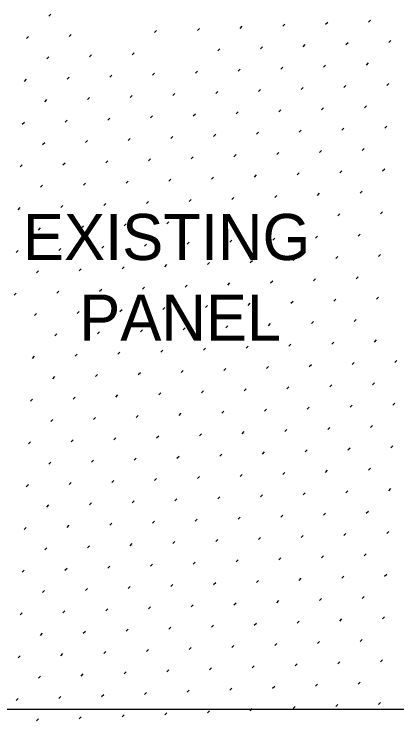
# Model space of a CAD drawing. Extents: x 49991.4 to 50021, y 49987.6 to 50011.4.
# Drawn here: x 50008.575 to 50009.239, y 49994.77 to 49995.997 of the extents above; entities that cross this region are included whole.
import ezdxf

# ---------------------------------------------------------------- set-up
doc = ezdxf.new("R2010")
doc.units = 0
for name, color, linetype in [('Level 1', 7, 'Continuous'), ('Level 10', 7, 'Continuous'), ('Level 2', 7, 'Continuous')]:
    doc.layers.add(name, color=color, linetype=linetype)

msp = doc.modelspace()

# ---------------------------------------------------------------- linework, layer by layer
at = {"layer": 'Level 1'}
msp.add_line((50007.9348, 49994.7903), (50009.8098, 49994.7903), dxfattribs=at)
at = {"layer": 'Level 10'}
for p, q in [((50008.6348, 49995.9936), (50008.6383, 49995.9972)), ((50009.1157, 49995.9795), (50009.1192, 49995.9831)), ((50009.1899, 49995.9831), (50009.1935, 49995.9866)), ((50008.8187, 49995.9654), (50008.8222, 49995.9689)), ((50008.8929, 49995.9689), (50008.8965, 49995.9724)), ((50008.9672, 49995.9724), (50008.9707, 49995.976)), ((50009.0414, 49995.976), (50009.045, 49995.9795)), ((50008.5959, 49995.9547), (50008.5994, 49995.9583)), ((50008.6702, 49995.9583), (50008.6737, 49995.9618)), ((50009.0768, 49995.9406), (50009.0803, 49995.9442)), ((50009.151, 49995.9442), (50009.1546, 49995.9477)), ((50009.2253, 49995.9477), (50009.2288, 49995.9513)), ((50008.9283, 49995.9335), (50008.9318, 49995.9371)), ((50009.0025, 49995.9371), (50009.0061, 49995.9406)), ((50008.6313, 49995.9194), (50008.6348, 49995.9229)), ((50008.7055, 49995.9229), (50008.7091, 49995.9265)), ((50008.7798, 49995.9265), (50008.7833, 49995.93)), ((50009.1121, 49995.9053), (50009.1157, 49995.9088)), ((50009.1864, 49995.9088), (50009.1899, 49995.9124)), ((50008.8894, 49995.8947), (50008.8929, 49995.8982)), ((50008.9636, 49995.8982), (50008.9672, 49995.9017)), ((50009.0379, 49995.9017), (50009.0414, 49995.9053)), ((50008.5924, 49995.8805), (50008.5959, 49995.884)), ((50008.6666, 49995.884), (50008.6702, 49995.8876)), ((50008.7409, 49995.8876), (50008.7444, 49995.8911)), ((50008.8151, 49995.8911), (50008.8187, 49995.8946)), ((50009.1475, 49995.8699), (50009.151, 49995.8735)), ((50009.2218, 49995.8735), (50009.2253, 49995.877)), ((50008.8505, 49995.8558), (50008.854, 49995.8593)), ((50008.9247, 49995.8593), (50008.9283, 49995.8628)), ((50008.999, 49995.8628), (50009.0025, 49995.8664)), ((50009.0732, 49995.8664), (50009.0768, 49995.8699)), ((50008.6277, 49995.8451), (50008.6313, 49995.8487)), ((50008.702, 49995.8487), (50008.7055, 49995.8522)), ((50008.7762, 49995.8522), (50008.7798, 49995.8557)), ((50009.1086, 49995.831), (50009.1121, 49995.8346)), ((50009.1829, 49995.8346), (50009.1864, 49995.8381)), ((50008.8858, 49995.8204), (50008.8894, 49995.8239)), ((50008.9601, 49995.8239), (50008.9636, 49995.8275)), ((50009.0343, 49995.8275), (50009.0379, 49995.831)), ((50008.5888, 49995.8062), (50008.5924, 49995.8098)), ((50008.6631, 49995.8098), (50008.6666, 49995.8133)), ((50008.7373, 49995.8133), (50008.7409, 49995.8168)), ((50008.8116, 49995.8169), (50008.8151, 49995.8204)), ((50009.144, 49995.7957), (50009.1475, 49995.7992)), ((50009.2182, 49995.7992), (50009.2217, 49995.8027)), ((50008.8469, 49995.7815), (50008.8505, 49995.785)), ((50008.9212, 49995.785), (50008.9247, 49995.7886)), ((50008.9954, 49995.7886), (50008.999, 49995.7921)), ((50009.0697, 49995.7921), (50009.0732, 49995.7957)), ((50008.6242, 49995.7709), (50008.6277, 49995.7744)), ((50008.6984, 49995.7744), (50008.702, 49995.778)), ((50008.7727, 49995.778), (50008.7762, 49995.7815)), ((50009.1051, 49995.7568), (50009.1086, 49995.7603)), ((50009.1793, 49995.7603), (50009.1828, 49995.7639)), ((50008.8823, 49995.7461), (50008.8858, 49995.7497)), ((50008.9565, 49995.7497), (50008.9601, 49995.7532)), ((50009.0308, 49995.7532), (50009.0343, 49995.7568)), ((50008.5853, 49995.732), (50008.5888, 49995.7355)), ((50008.6595, 49995.7355), (50008.6631, 49995.7391)), ((50008.7338, 49995.7391), (50008.7373, 49995.7426)), ((50008.808, 49995.7426), (50008.8116, 49995.7461)), ((50009.1404, 49995.7214), (50009.1439, 49995.725)), ((50009.2147, 49995.725), (50009.2182, 49995.7285)), ((50008.8434, 49995.7072), (50008.8469, 49995.7108)), ((50008.9177, 49995.7108), (50008.9212, 49995.7143)), ((50008.9919, 49995.7143), (50008.9954, 49995.7179)), ((50009.0662, 49995.7179), (50009.0697, 49995.7214)), ((50008.6206, 49995.6966), (50008.6242, 49995.7002)), ((50008.6949, 49995.7002), (50008.6984, 49995.7037)), ((50008.7691, 49995.7037), (50008.7727, 49995.7072)), ((50009.1758, 49995.6861), (50009.1793, 49995.6896)), ((50008.8788, 49995.6719), (50008.8823, 49995.6754)), ((50008.953, 49995.6754), (50008.9565, 49995.679)), ((50009.0273, 49995.679), (50009.0308, 49995.6825)), ((50009.1015, 49995.6825), (50009.105, 49995.6861)), ((50008.656, 49995.6613), (50008.6595, 49995.6648)), ((50008.7302, 49995.6648), (50008.7338, 49995.6683)), ((50008.8045, 49995.6683), (50008.808, 49995.6719)), ((50008.5817, 49995.6577), (50008.5853, 49995.6613)), ((50009.1369, 49995.6472), (50009.1404, 49995.6507)), ((50009.2111, 49995.6507), (50009.2147, 49995.6542)), ((50008.9141, 49995.6365), (50008.9176, 49995.6401)), ((50008.9884, 49995.6401), (50008.9919, 49995.6436)), ((50009.0626, 49995.6436), (50009.0662, 49995.6472)), ((50008.6171, 49995.6224), (50008.6206, 49995.6259)), ((50008.6913, 49995.6259), (50008.6949, 49995.6294)), ((50008.7656, 49995.6295), (50008.7691, 49995.633)), ((50008.8399, 49995.633), (50008.8434, 49995.6365)), ((50009.1722, 49995.6118), (50009.1758, 49995.6153)), ((50008.8752, 49995.5976), (50008.8787, 49995.6012)), ((50008.9495, 49995.6012), (50008.953, 49995.6047)), ((50009.0237, 49995.6047), (50009.0273, 49995.6083)), ((50009.098, 49995.6083), (50009.1015, 49995.6118)), ((50008.6525, 49995.587), (50008.656, 49995.5905)), ((50008.7267, 49995.5906), (50008.7302, 49995.5941)), ((50008.801, 49995.5941), (50008.8045, 49995.5976)), ((50008.5782, 49995.5835), (50008.5817, 49995.587)), ((50009.1333, 49995.5729), (50009.1369, 49995.5764)), ((50009.2076, 49995.5765), (50009.2111, 49995.58)), ((50008.9106, 49995.5623), (50008.9141, 49995.5658)), ((50008.9848, 49995.5658), (50008.9884, 49995.5694)), ((50009.0591, 49995.5694), (50009.0626, 49995.5729)), ((50008.6136, 49995.5481), (50008.6171, 49995.5516)), ((50008.6878, 49995.5517), (50008.6913, 49995.5552)), ((50008.7621, 49995.5552), (50008.7656, 49995.5587)), ((50008.8363, 49995.5587), (50008.8398, 49995.5623)), ((50009.1687, 49995.5376), (50009.1722, 49995.5411)), ((50008.8717, 49995.5234), (50008.8752, 49995.5269)), ((50008.9459, 49995.5269), (50008.9495, 49995.5305)), ((50009.0202, 49995.5305), (50009.0237, 49995.534)), ((50009.0944, 49995.534), (50009.098, 49995.5375)), ((50008.6489, 49995.5128), (50008.6524, 49995.5163)), ((50008.7232, 49995.5163), (50008.7267, 49995.5198)), ((50008.7974, 49995.5198), (50008.801, 49995.5234)), ((50008.5747, 49995.5092), (50008.5782, 49995.5128)), ((50009.1298, 49995.4987), (50009.1333, 49995.5022)), ((50009.204, 49995.5022), (50009.2076, 49995.5057)), ((50008.907, 49995.488), (50008.9106, 49995.4916)), ((50008.9813, 49995.4916), (50008.9848, 49995.4951)), ((50009.0555, 49995.4951), (50009.0591, 49995.4987)), ((50008.6843, 49995.4774), (50008.6878, 49995.4809)), ((50008.7585, 49995.4809), (50008.7621, 49995.4845)), ((50008.8328, 49995.4845), (50008.8363, 49995.488)), ((50008.61, 49995.4739), (50008.6135, 49995.4774)), ((50009.1651, 49995.4633), (50009.1687, 49995.4668)), ((50008.9424, 49995.4527), (50008.9459, 49995.4562)), ((50009.0166, 49995.4562), (50009.0202, 49995.4598)), ((50009.0909, 49995.4598), (50009.0944, 49995.4633)), ((50008.6454, 49995.4385), (50008.6489, 49995.442)), ((50008.7196, 49995.442), (50008.7232, 49995.4456)), ((50008.7939, 49995.4456), (50008.7974, 49995.4491)), ((50008.8681, 49995.4491), (50008.8717, 49995.4527)), ((50009.2005, 49995.4279), (50009.204, 49995.4315)), ((50008.9035, 49995.4138), (50008.907, 49995.4173)), ((50008.9777, 49995.4173), (50008.9813, 49995.4209)), ((50009.052, 49995.4209), (50009.0555, 49995.4244)), ((50009.1262, 49995.4244), (50009.1298, 49995.4279)), ((50008.6807, 49995.4031), (50008.6843, 49995.4067)), ((50008.755, 49995.4067), (50008.7585, 49995.4102)), ((50008.8292, 49995.4102), (50008.8328, 49995.4138)), ((50008.6065, 49995.3996), (50008.61, 49995.4031)), ((50009.1616, 49995.389), (50009.1651, 49995.3926)), ((50009.2359, 49995.3926), (50009.2394, 49995.3961)), ((50008.9388, 49995.3784), (50008.9424, 49995.382)), ((50009.0131, 49995.382), (50009.0166, 49995.3855)), ((50009.0873, 49995.3855), (50009.0909, 49995.389)), ((50008.6418, 49995.3643), (50008.6454, 49995.3678)), ((50008.7161, 49995.3678), (50008.7196, 49995.3713)), ((50008.7903, 49995.3713), (50008.7939, 49995.3749)), ((50008.8646, 49995.3749), (50008.8681, 49995.3784)), ((50009.197, 49995.3537), (50009.2005, 49995.3572)), ((50008.8999, 49995.3395), (50008.9035, 49995.3431)), ((50008.9742, 49995.3431), (50008.9777, 49995.3466)), ((50009.0484, 49995.3466), (50009.052, 49995.3501)), ((50009.1227, 49995.3502), (50009.1262, 49995.3537)), ((50008.6772, 49995.3289), (50008.6807, 49995.3324)), ((50008.7514, 49995.3324), (50008.755, 49995.336)), ((50008.8257, 49995.336), (50008.8292, 49995.3395)), ((50008.6029, 49995.3254), (50008.6065, 49995.3289)), ((50009.1581, 49995.3148), (50009.1616, 49995.3183)), ((50009.2323, 49995.3183), (50009.2358, 49995.3219)), ((50008.9353, 49995.3042), (50008.9388, 49995.3077)), ((50009.0095, 49995.3077), (50009.0131, 49995.3112)), ((50009.0838, 49995.3113), (50009.0873, 49995.3148)), ((50008.6383, 49995.29), (50008.6418, 49995.2935)), ((50008.7125, 49995.2935), (50008.7161, 49995.2971)), ((50008.7868, 49995.2971), (50008.7903, 49995.3006)), ((50008.861, 49995.3006), (50008.8646, 49995.3042)), ((50009.1934, 49995.2794), (50009.1969, 49995.283)), ((50008.9706, 49995.2688), (50008.9742, 49995.2723)), ((50009.0449, 49995.2724), (50009.0484, 49995.2759)), ((50009.1192, 49995.2759), (50009.1227, 49995.2794)), ((50008.6736, 49995.2546), (50008.6772, 49995.2582)), ((50008.7479, 49995.2582), (50008.7514, 49995.2617)), ((50008.8221, 49995.2617), (50008.8257, 49995.2653)), ((50008.8964, 49995.2653), (50008.8999, 49995.2688)), ((50008.5994, 49995.2511), (50008.6029, 49995.2546)), ((50009.2288, 49995.2441), (50009.2323, 49995.2476)), ((50008.9318, 49995.2299), (50008.9353, 49995.2335)), ((50009.006, 49995.2335), (50009.0095, 49995.237)), ((50009.0803, 49995.237), (50009.0838, 49995.2405)), ((50009.1545, 49995.2405), (50009.158, 49995.2441)), ((50008.709, 49995.2193), (50008.7125, 49995.2228)), ((50008.7832, 49995.2228), (50008.7868, 49995.2264)), ((50008.8575, 49995.2264), (50008.861, 49995.2299)), ((50008.6347, 49995.2157), (50008.6383, 49995.2193)), ((50009.1899, 49995.2052), (50009.1934, 49995.2087)), ((50008.9671, 49995.1946), (50008.9706, 49995.1981)), ((50009.0414, 49995.1981), (50009.0449, 49995.2016)), ((50009.1156, 49995.2016), (50009.1191, 49995.2052)), ((50008.6701, 49995.1804), (50008.6736, 49995.1839)), ((50008.7443, 49995.1839), (50008.7479, 49995.1875)), ((50008.8186, 49995.1875), (50008.8221, 49995.191)), ((50008.8929, 49995.191), (50008.8964, 49995.1946)), ((50008.5958, 49995.1768), (50008.5994, 49995.1804)), ((50009.2252, 49995.1698), (50009.2288, 49995.1734)), ((50008.9282, 49995.1557), (50008.9317, 49995.1592)), ((50009.0025, 49995.1592), (50009.006, 49995.1627)), ((50009.0767, 49995.1627), (50009.0803, 49995.1663)), ((50009.151, 49995.1663), (50009.1545, 49995.1698)), ((50008.7054, 49995.145), (50008.709, 49995.1486)), ((50008.7797, 49995.1486), (50008.7832, 49995.1521)), ((50008.854, 49995.1521), (50008.8575, 49995.1557)), ((50008.6312, 49995.1415), (50008.6347, 49995.145)), ((50009.1863, 49995.1309), (50009.1899, 49995.1345)), ((50008.9636, 49995.1203), (50008.9671, 49995.1238)), ((50009.0378, 49995.1238), (50009.0414, 49995.1274)), ((50009.1121, 49995.1274), (50009.1156, 49995.1309)), ((50008.6666, 49995.1061), (50008.6701, 49995.1097)), ((50008.7408, 49995.1097), (50008.7443, 49995.1132)), ((50008.8151, 49995.1132), (50008.8186, 49995.1168)), ((50008.8893, 49995.1168), (50008.8928, 49995.1203)), ((50008.5923, 49995.1026), (50008.5958, 49995.1061)), ((50009.2217, 49995.0956), (50009.2252, 49995.0991)), ((50008.9247, 49995.0814), (50008.9282, 49995.0849)), ((50008.9989, 49995.085), (50009.0025, 49995.0885)), ((50009.0732, 49995.0885), (50009.0767, 49995.092)), ((50009.1474, 49995.092), (50009.151, 49995.0956)), ((50008.7019, 49995.0708), (50008.7054, 49995.0743)), ((50008.7762, 49995.0743), (50008.7797, 49995.0779)), ((50008.8504, 49995.0779), (50008.8539, 49995.0814)), ((50008.6277, 49995.0672), (50008.6312, 49995.0708)), ((50008.96, 49995.0461), (50008.9636, 49995.0496)), ((50009.0343, 49995.0496), (50009.0378, 49995.0531)), ((50009.1085, 49995.0531), (50009.1121, 49995.0567)), ((50009.1828, 49995.0567), (50009.1863, 49995.0602)), ((50008.7373, 49995.0354), (50008.7408, 49995.039)), ((50008.8115, 49995.039), (50008.8151, 49995.0425)), ((50008.8858, 49995.0425), (50008.8893, 49995.046)), ((50008.5888, 49995.0283), (50008.5923, 49995.0319)), ((50008.663, 49995.0319), (50008.6665, 49995.0354)), ((50009.2181, 49995.0213), (50009.2217, 49995.0249)), ((50008.9954, 49995.0107), (50008.9989, 49995.0142)), ((50009.0696, 49995.0142), (50009.0732, 49995.0178)), ((50009.1439, 49995.0178), (50009.1474, 49995.0213)), ((50008.6984, 49994.9965), (50008.7019, 49995.0001)), ((50008.7726, 49995.0001), (50008.7762, 49995.0036)), ((50008.8469, 49995.0036), (50008.8504, 49995.0071)), ((50008.9211, 49995.0072), (50008.9247, 49995.0107)), ((50008.6241, 49994.993), (50008.6276, 49994.9965)), ((50008.9565, 49994.9718), (50008.96, 49994.9753)), ((50009.0307, 49994.9753), (50009.0343, 49994.9789)), ((50009.105, 49994.9789), (50009.1085, 49994.9824)), ((50009.1792, 49994.9824), (50009.1828, 49994.986)), ((50008.7337, 49994.9612), (50008.7373, 49994.9647)), ((50008.808, 49994.9647), (50008.8115, 49994.9683)), ((50008.8822, 49994.9683), (50008.8858, 49994.9718)), ((50008.5852, 49994.9541), (50008.5887, 49994.9576)), ((50008.6595, 49994.9576), (50008.663, 49994.9612)), ((50009.2146, 49994.9471), (50009.2181, 49994.9506)), ((50008.9918, 49994.9364), (50008.9954, 49994.94)), ((50009.0661, 49994.94), (50009.0696, 49994.9435)), ((50009.1403, 49994.9435), (50009.1439, 49994.9471)), ((50008.6948, 49994.9223), (50008.6984, 49994.9258)), ((50008.7691, 49994.9258), (50008.7726, 49994.9294)), ((50008.8433, 49994.9294), (50008.8469, 49994.9329)), ((50008.9176, 49994.9329), (50008.9211, 49994.9364)), ((50008.6206, 49994.9187), (50008.6241, 49994.9223)), ((50008.9529, 49994.8975), (50008.9565, 49994.9011)), ((50009.0272, 49994.9011), (50009.0307, 49994.9046)), ((50009.1014, 49994.9046), (50009.105, 49994.9082)), ((50009.1757, 49994.9082), (50009.1792, 49994.9117)), ((50008.7302, 49994.8869), (50008.7337, 49994.8905)), ((50008.8044, 49994.8905), (50008.808, 49994.894)), ((50008.8787, 49994.894), (50008.8822, 49994.8975)), ((50008.5817, 49994.8798), (50008.5852, 49994.8834)), ((50008.6559, 49994.8834), (50008.6595, 49994.8869)), ((50009.2111, 49994.8728), (50009.2146, 49994.8764)), ((50008.9883, 49994.8622), (50008.9918, 49994.8657)), ((50009.0625, 49994.8657), (50009.0661, 49994.8693)), ((50009.1368, 49994.8693), (50009.1403, 49994.8728)), ((50008.7655, 49994.8516), (50008.7691, 49994.8551)), ((50008.8398, 49994.8551), (50008.8433, 49994.8586)), ((50008.914, 49994.8586), (50008.9176, 49994.8622)), ((50008.617, 49994.8445), (50008.6206, 49994.848)), ((50008.6913, 49994.848), (50008.6948, 49994.8516)), ((50009.0236, 49994.8268), (50009.0272, 49994.8304)), ((50009.0979, 49994.8304), (50009.1014, 49994.8339)), ((50009.1722, 49994.8339), (50009.1757, 49994.8375)), ((50008.7266, 49994.8127), (50008.7302, 49994.8162)), ((50008.8009, 49994.8162), (50008.8044, 49994.8197)), ((50008.8751, 49994.8198), (50008.8787, 49994.8233)), ((50008.9494, 49994.8233), (50008.9529, 49994.8268)), ((50008.5781, 49994.8056), (50008.5817, 49994.8091)), ((50008.6524, 49994.8091), (50008.6559, 49994.8127)), ((50008.9847, 49994.7879), (50008.9883, 49994.7915)), ((50009.059, 49994.7915), (50009.0625, 49994.795)), ((50009.1333, 49994.795), (50009.1368, 49994.7986)), ((50009.2075, 49994.7986), (50009.211, 49994.8021)), ((50008.762, 49994.7773), (50008.7655, 49994.7808)), ((50008.8362, 49994.7809), (50008.8398, 49994.7844)), ((50008.9105, 49994.7844), (50008.914, 49994.7879)), ((50008.6135, 49994.7702), (50008.617, 49994.7738)), ((50008.6877, 49994.7738), (50008.6913, 49994.7773))]:
    msp.add_line(p, q, dxfattribs=at)

# ---------------------------------------------------------------- texts
at = {"layer": 'Level 2'}
for s, p in [('EXISTING', (50008.5899, 49995.5703)), ('PANEL', (50008.6877, 49995.4303))]:
    msp.add_text(s, height=0.08, dxfattribs=at).set_placement(p)

doc.saveas('drawing.dxf')
